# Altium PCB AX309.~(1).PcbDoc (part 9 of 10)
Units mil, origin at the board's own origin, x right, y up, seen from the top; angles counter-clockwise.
Board outline 5185 x 3614 mil, 4 copper layers (Top Layer, GND, Mid-Layer 1, Bottom Layer); 191 components, 352 nets, 1106 pads, 425 vias.
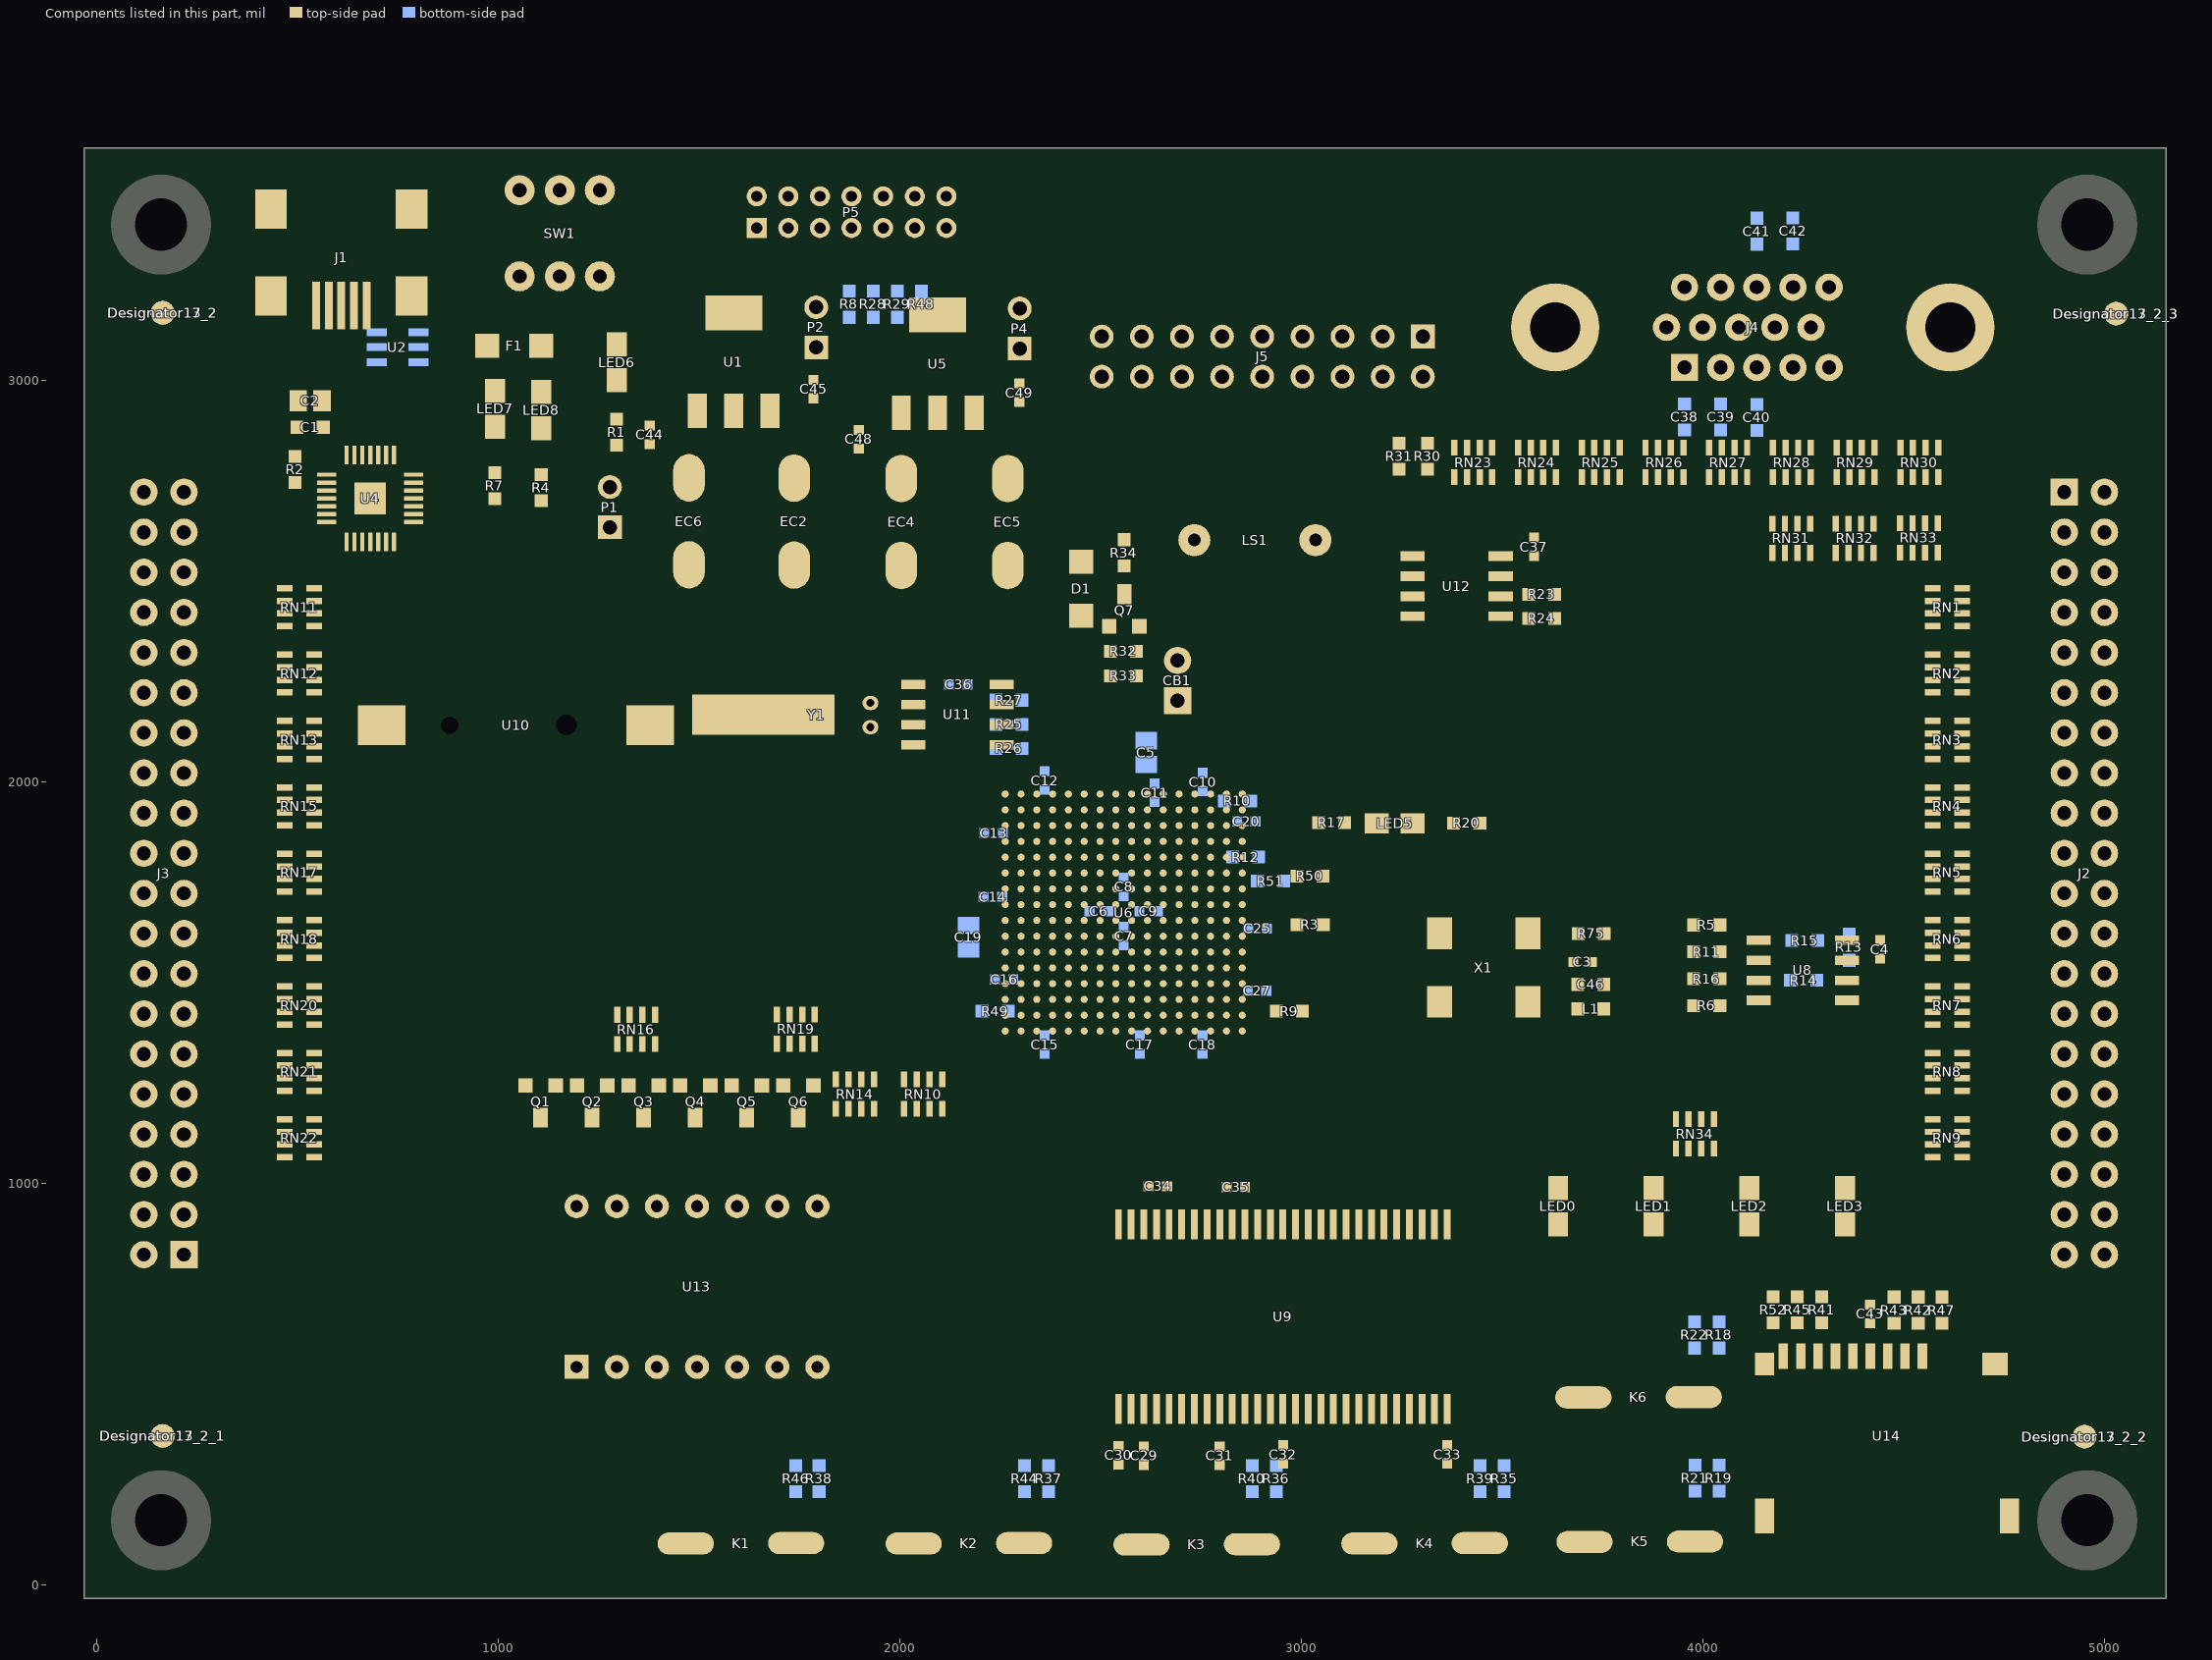
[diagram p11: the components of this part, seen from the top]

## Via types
v1: diameter 20, hole 10, Top Layer to Bottom Layer, 328 vias
v2: diameter 30, hole 15, Top Layer to Bottom Layer, 95 vias
v3: diameter 40, hole 20, Top Layer to Bottom Layer, 2 vias

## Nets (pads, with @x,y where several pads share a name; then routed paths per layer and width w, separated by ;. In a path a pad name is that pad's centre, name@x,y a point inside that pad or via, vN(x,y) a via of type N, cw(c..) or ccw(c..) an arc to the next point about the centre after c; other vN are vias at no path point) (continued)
copper on no net: (continued)
  Top Layer w0.7: 323.5,59.9 386.03,59.9 ; 323.5,60.6 386.03,60.6 ; 324.2,61.3 386.73,61.3 ; 324.2,62 387.43,62 ; 324.9,62.7 387.43,62.7 ; 324.9,63.4 388.13,63.4 ; 325.6,64.1 388.13,64.1 ; 325.6,64.8 388.83,64.8 ; 326.3,65.5 389.53,65.5 ; 326.3,66.2 389.53,66.2 ; 327,66.9 390.23,66.9 ; 327,67.6 390.93,67.6 ; 327.7,68.3 390.93,68.3 ; 327.7,69 391.63,69 ; 328.4,69.7 392.33,69.7 ; 329.1,70.4 393.03,70.4 ; 329.1,71.1 393.03,71.1 ; 329.8,71.8 393.73,71.8 ; 329.8,72.5 394.43,72.5 ; 330.5,73.2 395.13,73.2 ; 331.2,73.9 395.83,73.9 ; 331.2,74.6 395.83,74.6 ; 331.9,75.3 396.53,75.3 ; 331.9,76 397.23,76 ; 332.6,76.7 397.93,76.7 ; 333.3,77.4 398.63,77.4 ; 333.3,78.1 399.33,78.1 ; 334,78.8 400.03,78.8 ; 334.7,79.5 400.73,79.5 ; 335.4,80.2 400.73,80.2 ; 335.4,80.9 401.43,80.9 ; 336.1,81.6 402.13,81.6 ; 336.8,82.3 402.83,82.3 ; 336.8,83 403.53,83 ; 337.5,83.7 404.23,83.7 ; 338.2,84.4 404.93,84.4 ; 338.9,85.1 405.63,85.1 ; 338.9,85.8 407.03,85.8 ; 339.6,86.5 407.73,86.5 ; 340.3,87.2 408.43,87.2 ; 341,87.9 409.13,87.9 ; 341.7,88.6 409.83,88.6 ; 341.7,89.3 410.53,89.3 ; 342.4,90 411.23,90 ; 343.1,90.7 412.63,90.7 ; 343.8,91.4 413.33,91.4 ; 344.5,92.1 414.03,92.1 ; 345.2,92.8 414.73,92.8 ; 345.9,93.5 416.13,93.5 ; 345.9,94.2 416.83,94.2 ; 346.6,94.9 417.53,94.9 ; 347.3,95.6 418.93,95.6 ; 348,96.3 419.63,96.3 ; 348.7,97 421.03,97 ; 349.4,97.7 421.73,97.7 ; 350.1,98.4 423.13,98.4 ; 350.8,99.1 423.83,99.1 ; 351.5,99.8 425.23,99.8 ; 352.2,100.5 426.63,100.5 ; 352.9,101.2 427.33,101.2 ; 353.6,101.9 428.73,101.9 ; 354.3,102.6 430.13,102.6 ; 355,103.3 431.53,103.3 ; 355.7,104 432.23,104 ; 356.4,104.7 433.63,104.7 ; 357.1,105.4 435.03,105.4 ; 357.1,118.7 357.33,118.7 ; 357.8,106.1 436.43,106.1 ; 357.8,119.4 358.03,119.4 ; 357.8,120.1 359.43,120.1 ; 358.5,106.8 438.53,106.8 ; 358.5,120.8 360.13,120.8 ; 358.5,121.5 360.83,121.5 ; 359.2,122.2 361.53,122.2 ; 359.9,107.5 439.93,107.5 ; 359.9,122.9 362.23,122.9 ; 359.9,123.6 362.93,123.6 ; 360.6,108.2 441.33,108.2 ; 360.6,124.3 364.33,124.3 ; 360.6,125 365.03,125 ; 361.3,108.9 443.43,108.9 ; 361.3,125.7 365.73,125.7 ; 361.3,126.4 367.13,126.4 ; 362,109.6 444.83,109.6 ; 362,127.1 367.83,127.1 ; 362,127.8 368.53,127.8 ; 362.7,110.3 446.93,110.3 ; 362.7,128.5 369.93,128.5 ; 363.4,129.2 370.63,129.2 ; 363.4,129.9 371.33,129.9 ; 364.1,111 449.03,111 ; 364.1,130.6 372.73,130.6 ; 364.1,131.3 373.43,131.3 ; 364.8,111.7 451.13,111.7 ; 364.8,132 374.83,132 ; 364.8,132.7 375.53,132.7 ; 365.5,112.4 451.13,112.4 ; 365.5,133.4 376.93,133.4 ; 366.2,113.1 451.13,113.1 ; 366.2,134.1 377.63,134.1 ; 366.2,134.8 379.03,134.8 ; 366.9,135.5 380.43,135.5 ; 366.9,136.2 381.13,136.2 ; 367.6,113.8 451.13,113.8 ; 367.6,136.9 382.53,136.9 ; 367.6,137.6 383.93,137.6 ; 368.3,114.5 451.13,114.5 ; 368.3,138.3 384.63,138.3 ; 369,115.2 451.13,115.2 ; 369,139 386.03,139 ; 369,139.7 387.43,139.7 ; 369.7,140.4 388.83,140.4 ; 369.7,141.1 390.23,141.1 ; 370.4,115.9 451.13,115.9 ; 370.4,141.8 391.63,141.8 ; 370.4,142.5 393.03,142.5 ; 371.1,116.6 450.43,116.6 ; 371.1,143.2 394.43,143.2 ; 371.1,143.9 395.83,143.9 ; 371.8,117.3 450.43,117.3 ; 371.8,144.6 397.23,144.6 ; 372.5,145.3 399.33,145.3 ; 372.5,146 400.73,146 ; 373.2,118 450.43,118 ; 373.2,146.7 402.83,146.7 ; 373.2,147.4 404.23,147.4 ; 373.9,118.7 450.43,118.7 ; 373.9,148.1 406.33,148.1 ; 373.9,148.8 408.43,148.8 ; 374.6,149.5 409.83,149.5 ; 375.3,119.4 450.43,119.4 ; 375.3,150.2 412.63,150.2 ; 375.3,150.9 414.73,150.9 ; 376,120.1 450.43,120.1 ; 376,151.6 416.83,151.6 ; 376,152.3 419.63,152.3 ; 376.7,153 422.43,153 ; 376.7,153.7 425.23,153.7 ; 377.4,120.8 450.43,120.8 ; 377.4,154.4 428.73,154.4 ; 378.1,121.5 450.43,121.5 ; 378.1,155.1 430.83,155.1 ; 378.1,155.8 430.83,155.8 ; 378.8,156.5 431.53,156.5 ; 378.8,157.2 431.53,157.2 ; 379.5,122.2 450.43,122.2 ; 379.5,157.9 432.23,157.9 ; 379.5,158.6 432.23,158.6 ; 380.2,159.3 432.93,159.3 ; 380.2,160 432.93,160 ; 380.9,122.9 450.43,122.9 ; 380.9,160.7 432.93,160.7 ; 381.6,123.6 450.43,123.6 ; 381.6,161.4 433.63,161.4 ; 381.6,162.1 433.63,162.1 ; 382.3,162.8 434.33,162.8 ; 382.3,163.5 434.33,163.5 ; 383,124.3 450.43,124.3 ; 383,164.2 435.03,164.2 ; 383,164.9 435.03,164.9 ; 383.7,165.6 435.73,165.6 ; 384.4,125 450.43,125 ; 384.4,166.3 435.73,166.3 ; 384.4,167 436.43,167 ; 385.1,125.7 449.73,125.7 ; 385.1,167.7 436.43,167.7 ; 385.1,168.4 437.13,168.4 ; 385.8,169.1 437.13,169.1 ; 385.8,169.8 437.83,169.8 ; 386.5,126.4 449.73,126.4 ; 386.5,170.5 437.83,170.5 ; 387.2,171.2 438.53,171.2 ; 387.2,171.9 438.53,171.9 ; 387.9,127.1 449.73,127.1 ; 387.9,172.6 438.53,172.6 ; 387.9,173.3 439.23,173.3 ; 388.6,174 439.23,174 ; 388.6,174.7 439.93,174.7 ; 389.3,127.8 449.73,127.8 ; 389.3,175.4 439.93,175.4 ; 389.3,176.1 440.63,176.1 ; 390,176.8 440.63,176.8 ; 390.7,128.5 449.73,128.5 ; 390.7,177.5 441.33,177.5 ; 390.7,178.2 441.33,178.2 ; 391.4,178.9 442.03,178.9 ; 391.4,179.6 442.03,179.6 ; 392.1,129.2 449.73,129.2 ; 392.1,180.3 442.73,180.3 ; 392.1,181 442.73,181 ; 392.8,181.7 443.43,181.7 ; 393.5,129.9 449.73,129.9 ; 393.5,182.4 443.43,182.4 ; 393.5,183.1 444.13,183.1 ; 394.2,183.8 444.13,183.8 ; 394.2,184.5 444.83,184.5 ; 394.9,130.6 449.73,130.6 ; 394.9,185.2 444.83,185.2 ; 394.9,185.9 444.83,185.9 ; 395.6,186.6 445.53,186.6 ; 395.6,187.3 445.53,187.3 ; 396.3,131.3 449.73,131.3 ; 396.3,188 446.23,188 ; 397,188.7 446.23,188.7 ; 397,189.4 446.93,189.4 ; 397.7,132 449.73,132 ; 397.7,190.1 446.93,190.1 ; 397.7,190.8 447.63,190.8 ; 398.4,191.5 447.63,191.5 ; 398.4,192.2 448.33,192.2 ; 399.1,132.7 449.73,132.7 ; 399.1,192.9 448.33,192.9 ; 399.8,193.6 449.03,193.6 ; 399.8,194.3 449.03,194.3 ; 400.5,133.4 449.73,133.4 ; 400.5,195 449.73,195 ; 400.5,195.7 449.73,195.7 ; 401.2,196.4 450.43,196.4 ; 401.2,197.1 450.43,197.1 ; 401.9,197.8 497.33,197.8 ; 402.6,134.1 449.73,134.1 ; 402.6,198.5 497.33,198.5 ; 402.6,199.2 497.33,199.2 ; 403.3,199.9 497.33,199.9 ; 403.3,200.6 497.33,200.6 ; 404,134.8 449.73,134.8 ; 404,201.3 496.63,201.3 ; 404,202 496.63,202 ; 404.7,202.7 496.63,202.7 ; 404.7,203.4 496.63,203.4 ; 405.4,204.1 496.63,204.1 ; 406.1,135.5 449.03,135.5 ; 406.1,204.8 496.63,204.8 ; 406.1,205.5 495.93,205.5 ; 406.8,206.2 495.93,206.2 ; 406.8,206.9 495.93,206.9 ; 407.5,207.6 495.93,207.6 ; 407.5,208.3 495.93,208.3 ; 408.2,136.2 449.03,136.2 ; 408.2,209 495.93,209 ; 408.9,209.7 495.23,209.7 ; 408.9,210.4 495.23,210.4 ; 409.6,136.9 449.03,136.9 ; 409.6,211.1 495.23,211.1 ; 409.6,211.8 495.23,211.8 ; 410.3,212.5 495.23,212.5 ; 410.3,213.2 495.23,213.2 ; 411,213.9 494.53,213.9 ; 411.7,137.6 449.03,137.6 ; 411.7,214.6 494.53,214.6 ; 411.7,215.3 494.53,215.3 ; 412.4,216 494.53,216 ; 412.4,216.7 494.53,216.7 ; 413.1,217.4 494.53,217.4 ; 413.1,218.1 494.53,218.1 ; 413.8,138.3 449.03,138.3 ; 413.8,218.8 493.83,218.8 ; 413.8,219.5 493.83,219.5 ; 414.5,220.2 493.83,220.2 ; 415.2,220.9 493.83,220.9 ; 415.2,221.6 493.83,221.6 ; 415.9,139 449.03,139 ; 415.9,222.3 493.83,222.3 ; 415.9,223 493.13,223 ; 416.6,223.7 493.13,223.7 ; 416.6,224.4 493.13,224.4 ; 417.3,225.1 493.13,225.1 ; 418,225.8 493.13,225.8 ; 418,226.5 493.13,226.5 ; 418.7,139.7 449.03,139.7 ; 418.7,227.2 492.43,227.2 ; 418.7,227.9 492.43,227.9 ; 419.4,228.6 492.43,228.6 ; 419.4,229.3 492.43,229.3 ; 420.1,230 492.43,230 ; 420.1,230.7 492.43,230.7 ; 420.8,140.4 449.03,140.4 ; 420.8,231.4 492.43,231.4 ; 421.5,232.1 491.73,232.1 ; 421.5,232.8 491.73,232.8 ; 422.2,233.5 491.73,233.5 ; 422.2,234.2 491.73,234.2 ; 422.9,234.9 491.73,234.9 ; 422.9,235.6 491.73,235.6 ; 423.6,141.1 449.03,141.1 ; 423.6,236.3 491.03,236.3 ; 424.3,237 491.03,237 ; 424.3,237.7 491.03,237.7 ; 425,238.4 491.03,238.4 ; 425,239.1 491.03,239.1 ; 425.7,239.8 491.03,239.8 ; 425.7,240.5 490.33,240.5 ; 426.4,141.8 449.03,141.8 ; 426.4,241.2 490.33,241.2 ; 427.1,241.9 490.33,241.9 ; 427.1,242.6 490.33,242.6 ; 427.8,243.3 490.33,243.3 ; 427.8,244 490.33,244 ; 428.5,244.7 489.63,244.7 ; 428.5,245.4 489.63,245.4 ; 429.9,142.5 449.03,142.5 ; 433.4,143.2 449.03,143.2 ; 437.6,143.9 449.03,143.9 ; 442.5,144.6 448.33,144.6 ; 451.6,193.6 498.03,193.6 ; 451.6,194.3 498.03,194.3 ; 451.6,195 498.03,195 ; 451.6,195.7 498.03,195.7 ; 451.6,196.4 497.33,196.4 ; 451.6,197.1 497.33,197.1 ; 452.3,185.2 499.43,185.2 ; 452.3,185.9 499.43,185.9 ; 452.3,186.6 499.43,186.6 ; 452.3,187.3 499.43,187.3 ; 452.3,188 498.73,188 ; 452.3,188.7 498.73,188.7 ; 452.3,189.4 498.73,189.4 ; 452.3,190.1 498.73,190.1 ; 452.3,190.8 498.73,190.8 ; 452.3,191.5 498.73,191.5 ; 452.3,192.2 498.03,192.2 ; 452.3,192.9 498.03,192.9 ; 453,176.8 500.83,176.8 ; 453,177.5 500.83,177.5 ; 453,178.2 500.83,178.2 ; 453,178.9 500.13,178.9 ; 453,179.6 500.13,179.6 ; 453,180.3 500.13,180.3 ; 453,181 500.13,181 ; 453,181.7 500.13,181.7 ; 453,182.4 500.13,182.4 ; 453,183.1 499.43,183.1 ; 453,183.8 499.43,183.8 ; 453,184.5 499.43,184.5 ; 453.7,169.1 502.23,169.1 ; 453.7,169.8 502.23,169.8 ; 453.7,170.5 501.53,170.5 ; 453.7,171.2 501.53,171.2 ; 453.7,171.9 501.53,171.9 ; 453.7,172.6 501.53,172.6 ; 453.7,173.3 501.53,173.3 ; 453.7,174 501.53,174 ; 453.7,174.7 500.83,174.7 ; 453.7,175.4 500.83,175.4 ; 453.7,176.1 500.83,176.1 ; 454.4,160.7 503.63,160.7 ; 454.4,161.4 502.93,161.4 ; 454.4,162.1 502.93,162.1 ; 454.4,162.8 502.93,162.8 ; 454.4,163.5 502.93,163.5 ; 454.4,164.2 502.93,164.2 ; 454.4,164.9 502.93,164.9 ; 454.4,165.6 502.23,165.6 ; 454.4,166.3 502.23,166.3 ; 454.4,167 502.23,167 ; 454.4,167.7 502.23,167.7 ; 454.4,168.4 502.23,168.4 ; 455.1,152.3 504.33,152.3 ; 455.1,153 504.33,153 ; 455.1,153.7 504.33,153.7 ; 455.1,154.4 504.33,154.4 ; 455.1,155.1 504.33,155.1 ; 455.1,155.8 504.33,155.8 ; 455.1,156.5 504.33,156.5 ; 455.1,157.2 503.63,157.2 ; 455.1,157.9 503.63,157.9 ; 455.1,158.6 503.63,158.6 ; 455.1,159.3 503.63,159.3 ; 455.1,160 503.63,160 ; 455.8,144.6 505.73,144.6 ; 455.8,145.3 505.73,145.3 ; 455.8,146 505.73,146 ; 455.8,146.7 505.73,146.7 ; 455.8,147.4 505.73,147.4 ; 455.8,148.1 505.03,148.1 ; 455.8,148.8 505.03,148.8 ; 455.8,149.5 505.03,149.5 ; 455.8,150.2 505.03,150.2 ; 455.8,150.9 505.03,150.9 ; 455.8,151.6 505.03,151.6 ; 456.5,136.2 507.13,136.2 ; 456.5,136.9 507.13,136.9 ; 456.5,137.6 507.13,137.6 ; 456.5,138.3 507.13,138.3 ; 456.5,139 506.43,139 ; 456.5,139.7 506.43,139.7 ; 456.5,140.4 506.43,140.4 ; 456.5,141.1 506.43,141.1 ; 456.5,141.8 506.43,141.8 ; 456.5,142.5 506.43,142.5 ; 456.5,143.2 506.43,143.2 ; 456.5,143.9 505.73,143.9 ; 457.2,128.5 508.53,128.5 ; 457.2,129.2 508.53,129.2 ; 457.2,129.9 508.53,129.9 ; 457.2,130.6 507.83,130.6 ; 457.2,131.3 507.83,131.3 ; 457.2,132 507.83,132 ; 457.2,132.7 507.83,132.7 ; 457.2,133.4 507.83,133.4 ; 457.2,134.1 507.83,134.1 ; 457.2,134.8 507.13,134.8 ; 457.2,135.5 507.13,135.5 ; 457.9,120.1 509.93,120.1 ; 457.9,120.8 509.93,120.8 ; 457.9,121.5 509.23,121.5 ; 457.9,122.2 509.23,122.2 ; 457.9,122.9 509.23,122.9 ; 457.9,123.6 509.23,123.6 ; 457.9,124.3 509.23,124.3 ; 457.9,125 509.23,125 ; 457.9,125.7 509.23,125.7 ; 457.9,126.4 508.53,126.4 ; 457.9,127.1 508.53,127.1 ; 457.9,127.8 508.53,127.8 ; 458.6,112.4 511.33,112.4 ; 458.6,113.1 510.63,113.1 ; 458.6,113.8 510.63,113.8 ; 458.6,114.5 510.63,114.5 ; 458.6,115.2 510.63,115.2 ; 458.6,115.9 510.63,115.9 ; 458.6,116.6 510.63,116.6 ; 458.6,117.3 509.93,117.3 ; 458.6,118 509.93,118 ; 458.6,118.7 509.93,118.7 ; 458.6,119.4 509.93,119.4 ; 459.3,104 512.03,104 ; 459.3,104.7 512.03,104.7 ; 459.3,105.4 512.03,105.4 ; 459.3,106.1 512.03,106.1 ; 459.3,106.8 512.03,106.8 ; 459.3,107.5 512.03,107.5 ; 459.3,108.2 512.03,108.2 ; 459.3,108.9 511.33,108.9 ; 459.3,109.6 511.33,109.6 ; 459.3,110.3 511.33,110.3 ; 459.3,111 511.33,111 ; 459.3,111.7 511.33,111.7 ; 460,96.3 513.43,96.3 ; 460,97 513.43,97 ; 460,97.7 513.43,97.7 ; 460,98.4 513.43,98.4 ; 460,99.1 513.43,99.1 ; 460,99.8 512.73,99.8 ; 460,100.5 512.73,100.5 ; 460,101.2 512.73,101.2 ; 460,101.9 512.73,101.9 ; 460,102.6 512.73,102.6 ; 460,103.3 512.73,103.3 ; 460.7,87.9 514.83,87.9 ; 460.7,88.6 514.83,88.6 ; 460.7,89.3 514.83,89.3 ; 460.7,90 514.83,90 ; 460.7,90.7 514.13,90.7 ; 460.7,91.4 514.13,91.4 ; 460.7,92.1 514.13,92.1 ; 460.7,92.8 514.13,92.8 ; 460.7,93.5 514.13,93.5 ; 460.7,94.2 514.13,94.2 ; 460.7,94.9 514.13,94.9 ; 460.7,95.6 513.43,95.6 ; 461.4,80.2 516.23,80.2 ; 461.4,80.9 516.23,80.9 ; 461.4,81.6 516.23,81.6 ; 461.4,82.3 515.53,82.3 ; 461.4,83 515.53,83 ; 461.4,83.7 515.53,83.7 ; 461.4,84.4 515.53,84.4 ; 461.4,85.1 515.53,85.1 ; 461.4,85.8 515.53,85.8 ; 461.4,86.5 514.83,86.5 ; 461.4,87.2 514.83,87.2 ; 462.1,71.8 517.63,71.8 ; 462.1,72.5 517.63,72.5 ; 462.1,73.2 516.93,73.2 ; 462.1,73.9 516.93,73.9 ; 462.1,74.6 516.93,74.6 ; 462.1,75.3 516.93,75.3 ; 462.1,76 516.93,76 ; 462.1,76.7 516.93,76.7 ; 462.1,77.4 516.93,77.4 ; 462.1,78.1 516.23,78.1 ; 462.1,78.8 516.23,78.8 ; 462.1,79.5 516.23,79.5 ; 462.8,64.1 518.33,64.1 ; 462.8,64.8 518.33,64.8 ; 462.8,65.5 518.33,65.5 ; 462.8,66.2 518.33,66.2 ; 462.8,66.9 518.33,66.9 ; 462.8,67.6 518.33,67.6 ; 462.8,68.3 518.33,68.3 ; 462.8,69 517.63,69 ; 462.8,69.7 517.63,69.7 ; 462.8,70.4 517.63,70.4 ; 462.8,71.1 517.63,71.1 ; 463.5,59.9 519.03,59.9 ; 463.5,60.6 519.03,60.6 ; 463.5,61.3 519.03,61.3 ; 463.5,62 519.03,62 ; 463.5,62.7 519.03,62.7 ; 463.5,63.4 519.03,63.4 ; 558.7,59.9 708.73,59.9 ; 558.7,60.6 708.73,60.6 ; 558.7,61.3 708.73,61.3 ; 559.4,62 708.73,62 ; 559.4,62.7 708.73,62.7 ; 559.4,63.4 709.43,63.4 ; 559.4,64.1 709.43,64.1 ; 559.4,64.8 709.43,64.8 ; 560.1,65.5 709.43,65.5 ; 560.1,66.2 709.43,66.2 ; 560.1,66.9 710.13,66.9 ; 560.1,67.6 710.13,67.6 ; 560.1,68.3 710.13,68.3 ; 560.8,69 710.13,69 ; 560.8,69.7 710.13,69.7 ; 560.8,70.4 710.83,70.4 ; 560.8,71.1 710.83,71.1 ; 561.5,71.8 710.83,71.8 ; 561.5,72.5 710.83,72.5 ; 561.5,73.2 711.53,73.2 ; 561.5,73.9 711.53,73.9 ; 561.5,74.6 711.53,74.6 ; 562.2,75.3 711.53,75.3 ; 562.2,76 711.53,76 ; 562.2,76.7 712.23,76.7 ; 562.2,77.4 712.23,77.4 ; 562.2,78.1 712.23,78.1 ; 562.9,78.8 712.23,78.8 ; 562.9,79.5 712.23,79.5 ; 562.9,80.2 712.93,80.2 ; 562.9,80.9 712.93,80.9 ; 562.9,81.6 712.93,81.6 ; 563.6,82.3 712.93,82.3 ; 563.6,83 712.93,83 ; 563.6,83.7 713.63,83.7 ; 563.6,84.4 713.63,84.4 ; 564.3,85.1 713.63,85.1 ; 564.3,85.8 713.63,85.8 ; 564.3,86.5 714.33,86.5 ; 564.3,87.2 714.33,87.2 ; 564.3,87.9 714.33,87.9 ; 565,88.6 714.33,88.6 ; 565,89.3 714.33,89.3 ; 565,90 715.03,90 ; 565,90.7 715.03,90.7 ; 565,91.4 715.03,91.4 ; 565.7,92.1 715.03,92.1 ; 565.7,92.8 715.03,92.8 ; 565.7,93.5 715.73,93.5 ; 565.7,94.2 715.73,94.2 ; 566.4,94.9 715.73,94.9 ; 566.4,95.6 715.73,95.6 ; 566.4,96.3 715.73,96.3 ; 566.4,97 716.43,97 ; 566.4,97.7 716.43,97.7 ; 567.1,98.4 716.43,98.4 ; 567.1,99.1 716.43,99.1 ; 567.1,99.8 717.13,99.8 ; 567.1,100.5 717.13,100.5 ; 567.1,101.2 717.13,101.2 ; 567.8,101.9 717.13,101.9 ; 567.8,102.6 717.13,102.6 ; 567.8,103.3 717.83,103.3 ; 567.8,104 717.83,104 ; 567.8,104.7 717.83,104.7 ; 568.5,105.4 625.43,105.4 ; 568.5,106.1 625.43,106.1 ; 568.5,106.8 626.13,106.8 ; 568.5,107.5 626.13,107.5 ; 569.2,108.2 626.13,108.2 ; 569.2,108.9 626.13,108.9 ; 569.2,109.6 626.13,109.6 ; 569.2,110.3 626.83,110.3 ; 569.2,111 626.83,111 ; 569.9,111.7 626.83,111.7 ; 569.9,112.4 626.83,112.4 ; 569.9,113.1 626.83,113.1 ; 569.9,113.8 627.53,113.8 ; 569.9,114.5 627.53,114.5 ; 570.6,115.2 627.53,115.2 ; 570.6,115.9 627.53,115.9 ; 570.6,116.6 628.23,116.6 ; 570.6,117.3 628.23,117.3 ; 570.6,118 628.23,118 ; 571.3,118.7 628.23,118.7 ; 571.3,119.4 628.23,119.4 ; 571.3,120.1 628.93,120.1 ; 571.3,120.8 628.93,120.8 ; 572,121.5 628.93,121.5 ; 572,122.2 628.93,122.2 ; 572,122.9 628.93,122.9 ; 572,123.6 629.63,123.6 ; 572,124.3 629.63,124.3 ; 572.7,125 629.63,125 ; 572.7,125.7 629.63,125.7 ; 572.7,126.4 630.33,126.4 ; 572.7,127.1 630.33,127.1 ; 572.7,127.8 630.33,127.8 ; 573.4,128.5 630.33,128.5 ; 573.4,129.2 630.33,129.2 ; 573.4,129.9 631.03,129.9 ; 573.4,130.6 631.03,130.6 ; 574.1,131.3 631.03,131.3 ; 574.1,132 631.03,132 ; 574.1,132.7 631.03,132.7 ; 574.1,133.4 631.73,133.4 ; 574.1,134.1 631.73,134.1 ; 574.8,134.8 631.73,134.8 ; 574.8,135.5 631.73,135.5 ; 574.8,136.2 632.43,136.2 ; 574.8,136.9 632.43,136.9 ; 574.8,137.6 632.43,137.6 ; 575.5,138.3 632.43,138.3 ; 575.5,139 632.43,139 ; 575.5,139.7 633.13,139.7 ; 575.5,140.4 633.13,140.4 ; 576.2,141.1 633.13,141.1 ; 576.2,141.8 633.13,141.8 ; 576.2,142.5 633.13,142.5 ; 576.2,143.2 633.83,143.2 ; 576.2,143.9 633.83,143.9 ; 576.9,144.6 633.83,144.6 ; 576.9,145.3 633.83,145.3 ; 576.9,146 634.53,146 ; 576.9,146.7 634.53,146.7 ; 576.9,147.4 634.53,147.4 ; 577.6,148.1 634.53,148.1 ; 577.6,148.8 634.53,148.8 ; 577.6,149.5 635.23,149.5 ; 577.6,150.2 635.23,150.2 ; 577.6,150.9 635.23,150.9 ; 578.3,151.6 635.23,151.6 ; 578.3,152.3 635.23,152.3 ; 578.3,153 635.93,153 ; 578.3,153.7 635.93,153.7 ; 579,154.4 635.93,154.4 ; 579,155.1 635.93,155.1 ; 579,155.8 636.63,155.8 ; 579,156.5 636.63,156.5 ; 579,157.2 636.63,157.2 ; 579.7,157.9 636.63,157.9 ; 579.7,158.6 636.63,158.6 ; 579.7,159.3 637.33,159.3 ; 579.7,160 637.33,160 ; 579.7,160.7 637.33,160.7 ; 580.4,161.4 637.33,161.4 ; 580.4,162.1 637.33,162.1 ; 580.4,162.8 638.03,162.8 ; 580.4,163.5 638.03,163.5 ; 580.4,164.2 638.03,164.2 ; 581.1,164.9 638.03,164.9 ; 581.1,165.6 638.73,165.6 ; 581.1,166.3 638.73,166.3 ; 581.1,167 638.73,167 ; 581.8,167.7 638.73,167.7 ; 581.8,168.4 638.73,168.4 ; 581.8,169.1 639.43,169.1 ; 581.8,169.8 639.43,169.8 ; 581.8,170.5 639.43,170.5 ; 582.5,171.2 639.43,171.2 ; 582.5,171.9 639.43,171.9 ; 582.5,172.6 640.13,172.6 ; 582.5,173.3 640.13,173.3 ; 582.5,174 640.13,174 ; 583.2,174.7 640.13,174.7 ; 583.2,175.4 640.83,175.4 ; 583.2,176.1 640.83,176.1 ; 583.2,176.8 640.83,176.8 ; 583.9,177.5 640.83,177.5 ; 583.9,178.2 640.83,178.2 ; 583.9,178.9 641.53,178.9 ; 583.9,179.6 641.53,179.6 ; 583.9,180.3 641.53,180.3 ; 584.6,181 641.53,181 ; 584.6,181.7 641.53,181.7 ; 584.6,182.4 642.23,182.4 ; 584.6,183.1 642.23,183.1 ; 584.6,183.8 642.23,183.8 ; 585.3,184.5 642.23,184.5 ; 585.3,185.2 642.93,185.2 ; 585.3,185.9 642.93,185.9 ; 585.3,186.6 642.93,186.6 ; 586,187.3 642.93,187.3 ; 586,188 642.93,188 ; 586,188.7 643.63,188.7 ; 586,189.4 643.63,189.4 ; 586,190.1 643.63,190.1 ; 586.7,190.8 643.63,190.8 ; 586.7,191.5 643.63,191.5 ; 586.7,192.2 644.33,192.2 ; 586.7,192.9 644.33,192.9 ; 586.7,193.6 644.33,193.6 ; 587.4,194.3 644.33,194.3 ; 587.4,195 645.03,195 ; 587.4,195.7 645.03,195.7 ; 587.4,196.4 645.03,196.4 ; 587.4,197.1 645.03,197.1 ; 588.1,197.8 645.03,197.8 ; 588.1,198.5 645.73,198.5 ; 588.1,199.2 645.73,199.2 ; 588.1,199.9 645.73,199.9 ; 588.8,200.6 645.73,200.6 ; 588.8,201.3 645.73,201.3 ; 588.8,202 646.43,202 ; 588.8,202.7 646.43,202.7 ; 588.8,203.4 646.43,203.4 ; 589.5,204.1 646.43,204.1 ; 589.5,204.8 647.13,204.8 ; 589.5,205.5 647.13,205.5 ; 589.5,206.2 647.13,206.2 ; 589.5,206.9 647.13,206.9 ; 590.2,207.6 647.13,207.6 ; 590.2,208.3 647.83,208.3 ; 590.2,209 647.83,209 ; 590.2,209.7 647.83,209.7 ; 590.2,210.4 647.83,210.4 ; 590.9,211.1 647.83,211.1 ; 590.9,211.8 648.53,211.8 ; 590.9,212.5 648.53,212.5 ; 590.9,213.2 648.53,213.2 ; 591.6,213.9 648.53,213.9 ; 591.6,214.6 649.23,214.6 ; 591.6,215.3 649.23,215.3 ; 591.6,216 649.23,216 ; 591.6,216.7 649.23,216.7 ; 592.3,217.4 649.23,217.4 ; 592.3,218.1 649.93,218.1 ; 592.3,218.8 649.93,218.8 ; 592.3,219.5 649.93,219.5 ; 592.3,220.2 649.93,220.2 ; 593,220.9 649.93,220.9 ; 593,221.6 650.63,221.6 ; 593,222.3 650.63,222.3 ; 593,223 650.63,223 ; 593.7,223.7 650.63,223.7 ; 593.7,224.4 651.33,224.4 ; 593.7,225.1 651.33,225.1 ; 593.7,225.8 651.33,225.8 ; 593.7,226.5 651.33,226.5 ; 594.4,227.2 651.33,227.2 ; 594.4,227.9 652.03,227.9 ; 594.4,228.6 652.03,228.6 ; 594.4,229.3 652.03,229.3 ; 594.4,230 652.03,230 ; 595.1,230.7 652.03,230.7 ; 595.1,231.4 652.73,231.4 ; 595.1,232.1 652.73,232.1 ; 595.1,232.8 652.73,232.8 ; 595.1,233.5 652.73,233.5 ; 595.8,234.2 653.43,234.2 ; 595.8,234.9 653.43,234.9 ; 595.8,235.6 653.43,235.6 ; 595.8,236.3 653.43,236.3 ; 596.5,237 653.43,237 ; 596.5,237.7 654.13,237.7 ; 596.5,238.4 654.13,238.4 ; 596.5,239.1 654.13,239.1 ; 596.5,239.8 654.13,239.8 ; 597.2,240.5 654.83,240.5 ; 597.2,241.2 654.83,241.2 ; 597.2,241.9 654.83,241.9 ; 597.2,242.6 654.83,242.6 ; 597.2,243.3 654.83,243.3 ; 597.9,244 655.53,244 ; 597.9,244.7 655.53,244.7 ; 597.9,245.4 655.53,245.4 ; 752.6,59.9 810.23,59.9 ; 752.6,60.6 810.23,60.6 ; 752.6,61.3 810.23,61.3 ; 752.6,62 810.23,62 ; 752.6,62.7 810.93,62.7 ; 753.3,63.4 810.93,63.4 ; 753.3,64.1 810.93,64.1 ; 753.3,64.8 810.93,64.8 ; 753.3,65.5 811.63,65.5 ; 754,66.2 811.63,66.2 ; 754,66.9 811.63,66.9 ; 754,67.6 811.63,67.6 ; 754,68.3 811.63,68.3 ; 754,69 812.33,69 ; 754.7,69.7 812.33,69.7 ; 754.7,70.4 812.33,70.4 ; 754.7,71.1 812.33,71.1 ; 754.7,71.8 812.33,71.8 ; 754.7,72.5 813.03,72.5 ; 755.4,73.2 813.03,73.2 ; 755.4,73.9 813.03,73.9 ; 755.4,74.6 813.03,74.6 ; 755.4,75.3 813.73,75.3 ; 756.1,76 813.73,76 ; 756.1,76.7 813.73,76.7 ; 756.1,77.4 813.73,77.4 ; 756.1,78.1 813.73,78.1 ; 756.1,78.8 814.43,78.8 ; 756.8,79.5 814.43,79.5 ; 756.8,80.2 814.43,80.2 ; 756.8,80.9 814.43,80.9 ; 756.8,81.6 814.43,81.6 ; 756.8,82.3 815.13,82.3 ; 757.5,83 815.13,83 ; 757.5,83.7 815.13,83.7 ; 757.5,84.4 815.13,84.4 ; 757.5,85.1 815.83,85.1 ; 757.5,85.8 815.83,85.8 ; 758.2,86.5 815.83,86.5 ; 758.2,87.2 815.83,87.2 ; 758.2,87.9 815.83,87.9 ; 758.2,88.6 816.53,88.6 ; 758.9,89.3 816.53,89.3 ; 758.9,90 816.53,90 ; 758.9,90.7 816.53,90.7 ; 758.9,91.4 816.53,91.4 ; 758.9,92.1 817.23,92.1 ; 759.6,92.8 817.23,92.8 ; 759.6,93.5 817.23,93.5 ; 759.6,94.2 817.23,94.2 ; 759.6,94.9 817.93,94.9 ; 759.6,95.6 817.93,95.6 ; 760.3,96.3 817.93,96.3 ; 760.3,97 817.93,97 ; 760.3,97.7 817.93,97.7 ; 760.3,98.4 818.63,98.4 ; 761,99.1 818.63,99.1 ; 761,99.8 818.63,99.8 ; 761,100.5 818.63,100.5 ; 761,101.2 818.63,101.2 ; 761,101.9 819.33,101.9 ; 761.7,102.6 819.33,102.6 ; 761.7,103.3 819.33,103.3 ; 761.7,104 819.33,104 ; 761.7,104.7 819.33,104.7 ; 761.7,105.4 820.03,105.4 ; 762.4,106.1 820.03,106.1 ; 762.4,106.8 820.03,106.8 ; 762.4,107.5 820.03,107.5 ; 762.4,108.2 820.73,108.2 ; 763.1,108.9 820.73,108.9 ; 763.1,109.6 820.73,109.6 ; 763.1,110.3 820.73,110.3 ; 763.1,111 820.73,111 ; 763.1,111.7 821.43,111.7 ; 763.8,112.4 821.43,112.4 ; 763.8,113.1 821.43,113.1 ; 763.8,113.8 821.43,113.8 ; 763.8,114.5 821.43,114.5 ; 763.8,115.2 822.13,115.2 ; 764.5,115.9 822.13,115.9 ; 764.5,116.6 822.13,116.6 ; 764.5,117.3 822.13,117.3 ; 764.5,118 822.83,118 ; 765.2,118.7 822.83,118.7 ; 765.2,119.4 822.83,119.4 ; 765.2,120.1 822.83,120.1 ; 765.2,120.8 822.83,120.8 ; 765.2,121.5 823.53,121.5 ; 765.9,122.2 823.53,122.2 ; 765.9,122.9 823.53,122.9 ; 765.9,123.6 823.53,123.6 ; 765.9,124.3 823.53,124.3 ; 765.9,125 824.23,125 ; 766.6,125.7 824.23,125.7 ; 766.6,126.4 824.23,126.4 ; 766.6,127.1 824.23,127.1 ; 766.6,127.8 824.93,127.8 ; 767.3,128.5 824.93,128.5 ; 767.3,129.2 824.93,129.2 ; 767.3,129.9 824.93,129.9 ; 767.3,130.6 824.93,130.6 ; 767.3,131.3 825.63,131.3 ; 768,132 825.63,132 ; 768,132.7 825.63,132.7 ; 768,133.4 825.63,133.4 ; 768,134.1 826.33,134.1 ; 768,134.8 826.33,134.8 ; 768.7,135.5 826.33,135.5 ; 768.7,136.2 826.33,136.2 ; 768.7,136.9 826.33,136.9 ; 768.7,137.6 827.03,137.6 ; 769.4,138.3 827.03,138.3 ; 769.4,139 827.03,139 ; 769.4,139.7 827.03,139.7 ; 769.4,140.4 827.03,140.4 ; 769.4,141.1 827.73,141.1 ; 770.1,141.8 827.73,141.8 ; 770.1,142.5 827.73,142.5 ; 770.1,143.2 827.73,143.2 ; 770.1,143.9 828.43,143.9 ; 770.1,144.6 828.43,144.6 ; 770.8,145.3 828.43,145.3 ; 770.8,146 828.43,146 ; 770.8,146.7 828.43,146.7 ; 770.8,147.4 829.13,147.4 ; 771.5,148.1 829.13,148.1 ; 771.5,148.8 829.13,148.8 ; 771.5,149.5 829.13,149.5 ; 771.5,150.2 829.13,150.2 ; 771.5,150.9 829.83,150.9 ; 772.2,151.6 829.83,151.6 ; 772.2,152.3 829.83,152.3 ; 772.2,153 829.83,153 ; 772.2,153.7 829.83,153.7 ; 772.2,154.4 830.53,154.4 ; 772.9,155.1 830.53,155.1 ; 772.9,155.8 830.53,155.8 ; 772.9,156.5 830.53,156.5 ; 772.9,157.2 831.23,157.2 ; 773.6,157.9 831.23,157.9 ; 773.6,158.6 831.23,158.6 ; 773.6,159.3 831.23,159.3 ; 773.6,160 831.23,160 ; 773.6,160.7 831.93,160.7 ; 774.3,161.4 831.93,161.4 ; 774.3,162.1 831.93,162.1 ; 774.3,162.8 831.93,162.8 ; 774.3,163.5 831.93,163.5 ; 774.3,164.2 832.63,164.2 ; 775,164.9 832.63,164.9 ; 775,165.6 832.63,165.6 ; 775,166.3 832.63,166.3 ; 775,167 833.33,167 ; 775.7,167.7 833.33,167.7 ; 775.7,168.4 833.33,168.4 ; 775.7,169.1 833.33,169.1 ; 775.7,169.8 833.33,169.8 ; 775.7,170.5 834.03,170.5 ; 776.4,171.2 834.03,171.2 ; 776.4,171.9 834.03,171.9 ; 776.4,172.6 834.03,172.6 ; 776.4,173.3 834.73,173.3 ; 776.4,174 834.73,174 ; 777.1,174.7 834.73,174.7 ; 777.1,175.4 834.73,175.4 ; 777.1,176.1 834.73,176.1 ; 777.1,176.8 835.43,176.8 ; 777.8,177.5 835.43,177.5 ; 777.8,178.2 835.43,178.2 ; 777.8,178.9 835.43,178.9 ; 777.8,179.6 835.43,179.6 ; 777.8,180.3 836.13,180.3 ; 778.5,181 836.13,181 ; 778.5,181.7 836.13,181.7 ; 778.5,182.4 836.13,182.4 ; 778.5,183.1 836.13,183.1 ; 778.5,183.8 836.83,183.8 ; 779.2,184.5 836.83,184.5 ; 779.2,185.2 836.83,185.2 ; 779.2,185.9 836.83,185.9 ; 779.2,186.6 837.53,186.6 ; 779.9,187.3 837.53,187.3 ; 779.9,188 837.53,188 ; 779.9,188.7 837.53,188.7 ; 779.9,189.4 837.53,189.4 ; 779.9,190.1 838.23,190.1 ; 780.6,190.8 838.23,190.8 ; 780.6,191.5 838.23,191.5 ; 780.6,192.2 838.23,192.2 ; 780.6,192.9 838.23,192.9 ; 780.6,193.6 838.93,193.6 ; 781.3,194.3 838.93,194.3 ; 781.3,195 838.93,195 ; 781.3,195.7 838.93,195.7 ; 781.3,196.4 839.63,196.4 ; 782,197.1 839.63,197.1 ; 782,197.8 839.63,197.8 ; 782,198.5 839.63,198.5 ; 782,199.2 839.63,199.2 ; 782,199.9 840.33,199.9 ; 782.7,200.6 840.33,200.6 ; 782.7,201.3 840.33,201.3 ; 782.7,202 840.33,202 ; 782.7,202.7 840.33,202.7 ; 782.7,203.4 841.03,203.4 ; 783.4,204.1 841.03,204.1 ; 783.4,204.8 841.03,204.8 ; 783.4,205.5 841.03,205.5 ; 783.4,206.2 841.73,206.2 ; 784.1,206.9 841.73,206.9 ; 784.1,207.6 841.73,207.6 ; 784.1,208.3 841.73,208.3 ; 784.1,209 841.73,209 ; 784.1,209.7 842.43,209.7 ; 784.8,210.4 842.43,210.4 ; 784.8,211.1 842.43,211.1 ; 784.8,211.8 842.43,211.8 ; 784.8,212.5 843.13,212.5 ; 784.8,213.2 843.13,213.2 ; 785.5,213.9 843.13,213.9 ; 785.5,214.6 843.13,214.6 ; 785.5,215.3 843.13,215.3 ; 785.5,216 843.83,216 ; 786.2,216.7 843.83,216.7 ; 786.2,217.4 843.83,217.4 ; 786.2,218.1 843.83,218.1 ; 786.2,218.8 843.83,218.8 ; 786.2,219.5 844.53,219.5 ; 786.9,220.2 844.53,220.2 ; 786.9,220.9 844.53,220.9 ; 786.9,221.6 844.53,221.6 ; 786.9,222.3 844.53,222.3 ; 786.9,223 845.23,223 ; 787.6,223.7 845.23,223.7 ; 787.6,224.4 845.23,224.4 ; 787.6,225.1 845.23,225.1 ; 787.6,225.8 845.93,225.8 ; 788.3,226.5 845.93,226.5 ; 788.3,227.2 845.93,227.2 ; 788.3,227.9 845.93,227.9 ; 788.3,228.6 845.93,228.6 ; 788.3,229.3 846.63,229.3 ; 789,230 846.63,230 ; 789,230.7 846.63,230.7 ; 789,231.4 846.63,231.4 ; 789,232.1 846.63,232.1 ; 789,232.8 847.33,232.8 ; 789.7,233.5 847.33,233.5 ; 789.7,234.2 847.33,234.2 ; 789.7,234.9 847.33,234.9 ; 789.7,235.6 848.03,235.6 ; 790.4,236.3 848.03,236.3 ; 790.4,237 848.03,237 ; 790.4,237.7 848.03,237.7 ; 790.4,238.4 848.03,238.4 ; 790.4,239.1 848.73,239.1 ; 791.1,239.8 848.73,239.8 ; 791.1,240.5 848.73,240.5 ; 791.1,241.2 848.73,241.2 ; 791.1,241.9 848.73,241.9 ; 791.1,242.6 849.43,242.6 ; 791.8,243.3 849.43,243.3 ; 791.8,244 849.43,244 ; 791.8,244.7 849.43,244.7 ; 791.8,245.4 850.13,245.4 ; 868.1,59.9 921.53,59.9 ; 868.1,60.6 922.23,60.6 ; 868.8,61.3 922.23,61.3 ; 868.8,62 922.23,62 ; 868.8,62.7 922.23,62.7 ; 868.8,63.4 922.23,63.4 ; 868.8,64.1 922.93,64.1 ; 869.5,64.8 922.93,64.8 ; 869.5,65.5 922.93,65.5 ; 869.5,66.2 922.93,66.2 ; 869.5,66.9 923.63,66.9 ; 870.2,67.6 923.63,67.6 ; 870.2,68.3 923.63,68.3 ; 870.2,69 923.63,69 ; 870.2,69.7 923.63,69.7 ; 870.2,70.4 924.33,70.4 ; 870.9,71.1 924.33,71.1 ; 870.9,71.8 924.33,71.8 ; 870.9,72.5 924.33,72.5 ; 870.9,73.2 924.33,73.2 ; 870.9,73.9 925.03,73.9 ; 871.6,74.6 925.03,74.6 ; 871.6,75.3 925.03,75.3 ; 871.6,76 925.03,76 ; 871.6,76.7 925.73,76.7 ; 872.3,77.4 925.73,77.4 ; 872.3,78.1 925.73,78.1 ; 872.3,78.8 925.73,78.8 ; 872.3,79.5 925.73,79.5 ; 872.3,80.2 926.43,80.2 ; 873,80.9 926.43,80.9 ; 873,81.6 926.43,81.6 ; 873,82.3 926.43,82.3 ; 873,83 926.43,83 ; 873,83.7 927.13,83.7 ; 873.7,84.4 927.13,84.4 ; 873.7,85.1 927.13,85.1 ; 873.7,85.8 927.13,85.8 ; 873.7,86.5 927.83,86.5 ; 874.4,87.2 927.83,87.2 ; 874.4,87.9 927.83,87.9 ; 874.4,88.6 927.83,88.6 ; 874.4,89.3 927.83,89.3 ; 874.4,90 928.53,90 ; 875.1,90.7 928.53,90.7 ; 875.1,91.4 928.53,91.4 ; 875.1,92.1 928.53,92.1 ; 875.1,92.8 928.53,92.8 ; 875.1,93.5 929.23,93.5 ; 875.8,94.2 929.23,94.2 ; 875.8,94.9 929.23,94.9 ; 875.8,95.6 929.23,95.6 ; 875.8,96.3 929.93,96.3 ; 876.5,97 929.93,97 ; 876.5,97.7 929.93,97.7 ; 876.5,98.4 929.93,98.4 ; 876.5,99.1 929.93,99.1 ; 876.5,99.8 930.63,99.8 ; 877.2,100.5 930.63,100.5 ; 877.2,101.2 930.63,101.2 ; 877.2,101.9 930.63,101.9 ; 877.2,102.6 930.63,102.6 ; 877.2,103.3 931.33,103.3 ; 877.9,104 931.33,104 ; 877.9,104.7 931.33,104.7 ; 877.9,105.4 931.33,105.4 ; 877.9,106.1 932.03,106.1 ; 878.6,106.8 932.03,106.8 ; 878.6,107.5 932.03,107.5 ; 878.6,108.2 932.03,108.2 ; 878.6,108.9 932.03,108.9 ; 878.6,109.6 932.73,109.6 ; 879.3,110.3 932.73,110.3 ; 879.3,111 932.73,111 ; 879.3,111.7 932.73,111.7 ; 879.3,112.4 932.73,112.4 ; 880,113.1 933.43,113.1 ; 880,113.8 933.43,113.8 ; 880,114.5 933.43,114.5 ; 880,115.2 933.43,115.2 ; 880,115.9 934.13,115.9 ; 880.7,116.6 934.13,116.6 ; 880.7,117.3 934.13,117.3 ; 880.7,118 934.13,118 ; 880.7,118.7 934.13,118.7 ; 880.7,119.4 934.83,119.4 ; 881.4,120.1 934.83,120.1 ; 881.4,120.8 934.83,120.8 ; 881.4,121.5 934.83,121.5 ; 881.4,122.2 934.83,122.2 ; 882.1,122.9 935.53,122.9 ; 882.1,123.6 935.53,123.6 ; 882.1,124.3 935.53,124.3 ; 882.1,125 935.53,125 ; 882.1,125.7 935.53,125.7 ; 882.8,126.4 936.23,126.4 ; 882.8,127.1 936.23,127.1 ; 882.8,127.8 936.23,127.8 ; 882.8,128.5 936.23,128.5 ; 882.8,129.2 936.93,129.2 ; 883.5,129.9 936.93,129.9 ; 883.5,130.6 936.93,130.6 ; 883.5,131.3 936.93,131.3 ; 883.5,132 936.93,132 ; 884.2,132.7 937.63,132.7 ; 884.2,133.4 937.63,133.4 ; 884.2,134.1 937.63,134.1 ; 884.2,134.8 937.63,134.8 ; 884.2,135.5 937.63,135.5 ; 884.9,136.2 938.33,136.2 ; 884.9,136.9 938.33,136.9 ; 884.9,137.6 938.33,137.6 ; 884.9,138.3 938.33,138.3 ; 884.9,139 939.03,139 ; 885.6,139.7 939.03,139.7 ; 885.6,140.4 939.03,140.4 ; 885.6,141.1 939.03,141.1 ; 885.6,141.8 939.03,141.8 ; 886.3,142.5 939.73,142.5 ; 886.3,143.2 939.73,143.2 ; 886.3,143.9 939.73,143.9 ; 886.3,144.6 939.73,144.6 ; 886.3,145.3 939.73,145.3 ; 887,146 940.43,146 ; 887,146.7 940.43,146.7 ; 887,147.4 940.43,147.4 ; 887,148.1 940.43,148.1 ; 887,148.8 941.13,148.8 ; 887.7,149.5 941.13,149.5 ; 887.7,150.2 941.13,150.2 ; 887.7,150.9 941.13,150.9 ; 887.7,151.6 941.13,151.6 ; 888.4,152.3 941.83,152.3 ; 888.4,153 941.83,153 ; 888.4,153.7 941.83,153.7 ; 888.4,154.4 941.83,154.4 ; 888.4,155.1 941.83,155.1 ; 889.1,155.8 942.53,155.8 ; 889.1,156.5 942.53,156.5 ; 889.1,157.2 942.53,157.2 ; 889.1,157.9 942.53,157.9 ; 889.1,158.6 943.23,158.6 ; 889.8,159.3 943.23,159.3 ; 889.8,160 943.23,160 ; 889.8,160.7 943.23,160.7 ; 889.8,161.4 943.23,161.4 ; 890.5,162.1 943.93,162.1 ; 890.5,162.8 943.93,162.8 ; 890.5,163.5 943.93,163.5 ; 890.5,164.2 943.93,164.2 ; 890.5,164.9 943.93,164.9 ; 891.2,165.6 944.63,165.6 ; 891.2,166.3 944.63,166.3 ; 891.2,167 944.63,167 ; 891.2,167.7 994.33,167.7 ; 891.2,168.4 994.33,168.4 ; 891.9,169.1 993.63,169.1 ; 891.9,169.8 993.63,169.8 ; 891.9,170.5 993.63,170.5 ; 891.9,171.2 992.93,171.2 ; 892.6,171.9 992.93,171.9 ; 892.6,172.6 992.23,172.6 ; 892.6,173.3 992.23,173.3 ; 892.6,174 991.53,174 ; 892.6,174.7 991.53,174.7 ; 893.3,175.4 991.53,175.4 ; 893.3,176.1 990.83,176.1 ; 893.3,176.8 990.83,176.8 ; 893.3,177.5 990.13,177.5 ; 893.3,178.2 990.13,178.2 ; 894,178.9 989.43,178.9 ; 894,179.6 989.43,179.6 ; 894,180.3 989.43,180.3 ; 894,181 988.73,181 ; 894.7,181.7 988.73,181.7 ; 894.7,182.4 988.03,182.4 ; 894.7,183.1 988.03,183.1 ; 894.7,183.8 988.03,183.8 ; 894.7,184.5 987.33,184.5 ; 895.4,185.2 987.33,185.2 ; 895.4,185.9 986.63,185.9 ; 895.4,186.6 986.63,186.6 ; 895.4,187.3 985.93,187.3 ; 895.4,188 985.93,188 ; 896.1,188.7 985.93,188.7 ; 896.1,189.4 985.23,189.4 ; 896.1,190.1 985.23,190.1 ; 896.1,190.8 984.53,190.8 ; 896.8,191.5 984.53,191.5 ; 896.8,192.2 983.83,192.2 ; 896.8,192.9 983.83,192.9 ; 896.8,193.6 983.83,193.6 ; 896.8,194.3 983.13,194.3 ; 897.5,195 983.13,195 ; 897.5,195.7 982.43,195.7 ; 897.5,196.4 982.43,196.4 ; 897.5,197.1 981.73,197.1 ; 897.5,197.8 981.73,197.8 ; 898.2,198.5 981.73,198.5 ; 898.2,199.2 981.03,199.2 ; 898.2,199.9 981.03,199.9 ; 898.2,200.6 980.33,200.6 ; 898.9,201.3 980.33,201.3 ; 898.9,202 980.33,202 ; 898.9,202.7 979.63,202.7 ; 898.9,203.4 979.63,203.4 ; 898.9,204.1 978.93,204.1 ; 899.6,204.8 978.93,204.8 ; 899.6,205.5 978.23,205.5 ; 899.6,206.2 978.23,206.2 ; 899.6,206.9 978.23,206.9 ; 899.6,207.6 977.53,207.6 ; 900.3,208.3 977.53,208.3 ; 900.3,209 976.83,209 ; 900.3,209.7 976.83,209.7 ; 900.3,210.4 976.13,210.4 ; 901,211.1 976.13,211.1 ; 901,211.8 976.13,211.8 ; 901,212.5 975.43,212.5 ; 901,213.2 975.43,213.2 ; 901,213.9 974.73,213.9 ; 901.7,214.6 974.73,214.6 ; 901.7,215.3 974.03,215.3 ; 901.7,216 974.03,216 ; 901.7,216.7 974.03,216.7 ; 901.7,217.4 973.33,217.4 ; 902.4,218.1 973.33,218.1 ; 902.4,218.8 972.63,218.8 ; 902.4,219.5 972.63,219.5 ; 902.4,220.2 972.63,220.2 ; 903.1,220.9 971.93,220.9 ; 903.1,221.6 971.93,221.6 ; 903.1,222.3 971.23,222.3 ; 903.1,223 971.23,223 ; 903.1,223.7 970.53,223.7 ; 903.8,224.4 970.53,224.4 ; 903.8,225.1 970.53,225.1 ; 903.8,225.8 969.83,225.8 ; 903.8,226.5 969.83,226.5 ; 904.5,227.2 969.13,227.2 ; 904.5,227.9 969.13,227.9 ; 904.5,228.6 968.43,228.6 ; 904.5,229.3 968.43,229.3 ; 904.5,230 968.43,230 ; 905.2,230.7 967.73,230.7 ; 905.2,231.4 967.73,231.4 ; 905.2,232.1 967.03,232.1 ; 905.2,232.8 967.03,232.8 ; 905.2,233.5 966.33,233.5 ; 905.9,234.2 966.33,234.2 ; 905.9,234.9 966.33,234.9 ; 905.9,235.6 965.63,235.6 ; 905.9,236.3 965.63,236.3 ; 906.6,237 964.93,237 ; 906.6,237.7 964.93,237.7 ; 906.6,238.4 964.93,238.4 ; 906.6,239.1 964.23,239.1 ; 906.6,239.8 964.23,239.8 ; 907.3,240.5 963.53,240.5 ; 907.3,241.2 963.53,241.2 ; 907.3,241.9 962.83,241.9 ; 907.3,242.6 962.83,242.6 ; 907.3,243.3 962.83,243.3 ; 908,244 962.13,244 ; 908,244.7 962.13,244.7 ; 908,245.4 961.43,245.4 ; 946.5,165.6 995.73,165.6 ; 946.5,166.3 995.03,166.3 ; 946.5,167 995.03,167 ; 947.2,164.2 995.73,164.2 ; 947.2,164.9 995.73,164.9 ; 947.9,162.8 996.43,162.8 ; 947.9,163.5 996.43,163.5 ; 948.6,160.7 997.13,160.7 ; 948.6,161.4 997.13,161.4 ; 948.6,162.1 997.13,162.1 ; 949.3,159.3 997.83,159.3 ; 949.3,160 997.83,160 ; 950,157.9 998.53,157.9 ; 950,158.6 998.53,158.6 ; 950.7,155.8 999.23,155.8 ; 950.7,156.5 999.23,156.5 ; 950.7,157.2 999.23,157.2 ; 951.4,154.4 999.93,154.4 ; 951.4,155.1 999.93,155.1 ; 952.1,152.3 1001.33,152.3 ; 952.1,153 1000.63,153 ; 952.1,153.7 1000.63,153.7 ; 952.8,150.9 1001.33,150.9 ; 952.8,151.6 1001.33,151.6 ; 953.5,149.5 1002.03,149.5 ; 953.5,150.2 1002.03,150.2 ; 954.2,147.4 1002.73,147.4 ; 954.2,148.1 1002.73,148.1 ; 954.2,148.8 1002.73,148.8 ; 954.9,146 1003.43,146 ; 954.9,146.7 1003.43,146.7 ; 955.6,144.6 1004.13,144.6 ; 955.6,145.3 1004.13,145.3 ; 956.3,142.5 1004.83,142.5 ; 956.3,143.2 1004.83,143.2 ; 956.3,143.9 1004.83,143.9 ; 957,141.1 1005.53,141.1 ; 957,141.8 1005.53,141.8 ; 957.7,139.7 1006.23,139.7 ; 957.7,140.4 1006.23,140.4 ; 958.4,137.6 1006.93,137.6 ; 958.4,138.3 1006.93,138.3 ; 958.4,139 1006.93,139 ; 959.1,136.2 1062.23,136.2 ; 959.1,136.9 1062.23,136.9 ; 959.8,134.8 1061.53,134.8 ; 959.8,135.5 1061.53,135.5 ; 960.5,132.7 1061.53,132.7 ; 960.5,133.4 1061.53,133.4 ; 960.5,134.1 1061.53,134.1 ; 961.2,131.3 1060.83,131.3 ; 961.2,132 1060.83,132 ; 961.9,129.9 1060.83,129.9 ; 961.9,130.6 1060.83,130.6 ; 962.6,127.8 1060.13,127.8 ; 962.6,128.5 1060.13,128.5 ; 962.6,129.2 1060.83,129.2 ; 963.3,126.4 1060.13,126.4 ; 963.3,127.1 1060.13,127.1 ; 964,125 1059.43,125 ; 964,125.7 1059.43,125.7 ; 964.7,122.9 1059.43,122.9 ; 964.7,123.6 1059.43,123.6 ; 964.7,124.3 1059.43,124.3 ; 965.4,121.5 1058.73,121.5 ; 965.4,122.2 1058.73,122.2 ; 966.1,120.1 1058.73,120.1 ; 966.1,120.8 1058.73,120.8 ; 966.8,118 1058.03,118 ; 966.8,118.7 1058.03,118.7 ; 966.8,119.4 1058.73,119.4 ; 967.5,116.6 1058.03,116.6 ; 967.5,117.3 1058.03,117.3 ; 968.2,115.2 1057.33,115.2 ; 968.2,115.9 1057.33,115.9 ; 968.9,113.1 1057.33,113.1 ; 968.9,113.8 1057.33,113.8 ; 968.9,114.5 1057.33,114.5 ; 969.6,111.7 1056.63,111.7 ; 969.6,112.4 1056.63,112.4 ; 970.3,110.3 1056.63,110.3 ; 970.3,111 1056.63,111 ; 971,108.2 1055.93,108.2 ; 971,108.9 1055.93,108.9 ; 971,109.6 1056.63,109.6 ; 971.7,106.8 1055.93,106.8 ; 971.7,107.5 1055.93,107.5 ; 972.4,104.7 1055.23,104.7 ; 972.4,105.4 1055.23,105.4 ; 972.4,106.1 1055.23,106.1 ; 973.1,103.3 1055.23,103.3 ; 973.1,104 1055.23,104 ; 973.8,101.9 1054.53,101.9 ; 973.8,102.6 1054.53,102.6 ; 974.5,99.8 1053.83,99.8 ; 974.5,100.5 1054.53,100.5 ; 974.5,101.2 1054.53,101.2 ; 975.2,98.4 1053.83,98.4 ; 975.2,99.1 1053.83,99.1 ; 975.9,97 1053.83,97 ; 975.9,97.7 1053.83,97.7 ; 976.6,94.9 1053.13,94.9 ; 976.6,95.6 1053.13,95.6 ; 976.6,96.3 1053.13,96.3 ; 977.3,93.5 1053.13,93.5 ; 977.3,94.2 1053.13,94.2 ; 978,92.1 1052.43,92.1 ; 978,92.8 1052.43,92.8 ; 978.7,90 1052.43,90 ; 978.7,90.7 1052.43,90.7 ; 978.7,91.4 1052.43,91.4 ; 979.4,88.6 1051.73,88.6 ; 979.4,89.3 1051.73,89.3 ; 980.1,87.2 1051.73,87.2 ; 980.1,87.9 1051.73,87.9 ; 980.8,85.1 1051.03,85.1 ; 980.8,85.8 1051.03,85.8 ; 980.8,86.5 1051.03,86.5 ; 981.5,83.7 1051.03,83.7 ; 981.5,84.4 1051.03,84.4 ; 982.2,82.3 1050.33,82.3 ; 982.2,83 1050.33,83 ; 982.9,80.2 1049.63,80.2 ; 982.9,80.9 1050.33,80.9 ; 982.9,81.6 1050.33,81.6 ; 983.6,78.8 1049.63,78.8 ; 983.6,79.5 1049.63,79.5 ; 984.3,77.4 1049.63,77.4 ; 984.3,78.1 1049.63,78.1 ; 985,75.3 1048.93,75.3 ; 985,76 1048.93,76 ; 985,76.7 1048.93,76.7 ; 985.7,73.9 1048.93,73.9 ; 985.7,74.6 1048.93,74.6 ; 986.4,72.5 1048.23,72.5 ; 986.4,73.2 1048.23,73.2 ; 987.1,70.4 1047.53,70.4 ; 987.1,71.1 1048.23,71.1 ; 987.1,71.8 1048.23,71.8 ; 987.8,69 1047.53,69 ; 987.8,69.7 1047.53,69.7 ; 988.5,67.6 1047.53,67.6 ; 988.5,68.3 1047.53,68.3 ; 989.2,65.5 1046.83,65.5 ; 989.2,66.2 1046.83,66.2 ; 989.2,66.9 1046.83,66.9 ; 989.9,64.1 1046.83,64.1 ; 989.9,64.8 1046.83,64.8 ; 990.6,62 1046.13,62 ; 990.6,62.7 1046.13,62.7 ; 990.6,63.4 1046.13,63.4 ; 991.3,60.6 1045.43,60.6 ; 991.3,61.3 1046.13,61.3 ; 992,59.9 1045.43,59.9 ; 1008.8,137.6 1062.23,137.6 ; 1008.8,138.3 1062.23,138.3 ; 1008.8,139 1062.93,139 ; 1008.8,139.7 1062.93,139.7 ; 1009.5,140.4 1062.93,140.4 ; 1009.5,141.1 1062.93,141.1 ; 1009.5,141.8 1062.93,141.8 ; 1009.5,142.5 1063.63,142.5 ; 1010.2,143.2 1063.63,143.2 ; 1010.2,143.9 1063.63,143.9 ; 1010.2,144.6 1063.63,144.6 ; 1010.2,145.3 1064.33,145.3 ; 1010.2,146 1064.33,146 ; 1010.9,146.7 1064.33,146.7 ; 1010.9,147.4 1064.33,147.4 ; 1010.9,148.1 1064.33,148.1 ; 1010.9,148.8 1065.03,148.8 ; 1010.9,149.5 1065.03,149.5 ; 1011.6,150.2 1065.03,150.2 ; 1011.6,150.9 1065.03,150.9 ; 1011.6,151.6 1065.03,151.6 ; 1011.6,152.3 1065.73,152.3 ; 1011.6,153 1065.73,153 ; 1012.3,153.7 1065.73,153.7 ; 1012.3,154.4 1065.73,154.4 ; 1012.3,155.1 1065.73,155.1 ; 1012.3,155.8 1066.43,155.8 ; 1013,156.5 1066.43,156.5 ; 1013,157.2 1066.43,157.2 ; 1013,157.9 1066.43,157.9 ; 1013,158.6 1067.13,158.6 ; 1013,159.3 1067.13,159.3 ; 1013.7,160 1067.13,160 ; 1013.7,160.7 1067.13,160.7 ; 1013.7,161.4 1067.13,161.4 ; 1013.7,162.1 1067.83,162.1 ; 1014.4,162.8 1067.83,162.8 ; 1014.4,163.5 1067.83,163.5 ; 1014.4,164.2 1067.83,164.2 ; 1014.4,164.9 1067.83,164.9 ; 1014.4,165.6 1068.53,165.6 ; 1015.1,166.3 1068.53,166.3 ; 1015.1,167 1068.53,167 ; 1015.1,167.7 1068.53,167.7 ; 1015.1,168.4 1069.23,168.4 ; 1015.1,169.1 1069.23,169.1 ; 1015.8,169.8 1069.23,169.8 ; 1015.8,170.5 1069.23,170.5 ; 1015.8,171.2 1069.23,171.2 ; 1015.8,171.9 1069.93,171.9 ; 1016.5,172.6 1069.93,172.6 ; 1016.5,173.3 1069.93,173.3 ; 1016.5,174 1069.93,174 ; 1016.5,174.7 1069.93,174.7 ; 1016.5,175.4 1070.63,175.4 ; 1017.2,176.1 1070.63,176.1 ; 1017.2,176.8 1070.63,176.8 ; 1017.2,177.5 1070.63,177.5 ; 1017.2,178.2 1071.33,178.2 ; 1017.2,178.9 1071.33,178.9 ; 1017.9,179.6 1071.33,179.6 ; 1017.9,180.3 1071.33,180.3 ; 1017.9,181 1071.33,181 ; 1017.9,181.7 1072.03,181.7 ; 1018.6,182.4 1072.03,182.4 ; 1018.6,183.1 1072.03,183.1 ; 1018.6,183.8 1072.03,183.8 ; 1018.6,184.5 1072.73,184.5 ; 1018.6,185.2 1072.73,185.2 ; 1019.3,185.9 1072.73,185.9 ; 1019.3,186.6 1072.73,186.6 ; 1019.3,187.3 1072.73,187.3 ; 1019.3,188 1073.43,188 ; 1019.3,188.7 1073.43,188.7 ; 1020,189.4 1073.43,189.4 ; 1020,190.1 1073.43,190.1 ; 1020,190.8 1073.43,190.8 ; 1020,191.5 1074.13,191.5 ; 1020.7,192.2 1074.13,192.2 ; 1020.7,192.9 1074.13,192.9 ; 1020.7,193.6 1074.13,193.6 ; 1020.7,194.3 1074.83,194.3 ; 1020.7,195 1074.83,195 ; 1021.4,195.7 1074.83,195.7 ; 1021.4,196.4 1074.83,196.4 ; 1021.4,197.1 1074.83,197.1 ; 1021.4,197.8 1075.53,197.8 ; 1022.1,198.5 1075.53,198.5 ; 1022.1,199.2 1075.53,199.2 ; 1022.1,199.9 1075.53,199.9 ; 1022.1,200.6 1075.53,200.6 ; 1022.1,201.3 1076.23,201.3 ; 1022.8,202 1076.23,202 ; 1022.8,202.7 1076.23,202.7 ; 1022.8,203.4 1076.23,203.4 ; 1022.8,204.1 1076.93,204.1 ; 1022.8,204.8 1076.93,204.8 ; 1023.5,205.5 1076.93,205.5 ; 1023.5,206.2 1076.93,206.2 ; 1023.5,206.9 1076.93,206.9 ; 1023.5,207.6 1077.63,207.6 ; 1024.2,208.3 1077.63,208.3 ; 1024.2,209 1077.63,209 ; 1024.2,209.7 1077.63,209.7 ; 1024.2,210.4 1077.63,210.4 ; 1024.2,211.1 1078.33,211.1 ; 1024.9,211.8 1078.33,211.8 ; 1024.9,212.5 1078.33,212.5 ; 1024.9,213.2 1078.33,213.2 ; 1024.9,213.9 1079.03,213.9 ; 1024.9,214.6 1079.03,214.6 ; 1025.6,215.3 1079.03,215.3 ; 1025.6,216 1079.03,216 ; 1025.6,216.7 1079.03,216.7 ; 1025.6,217.4 1079.73,217.4 ; 1026.3,218.1 1079.73,218.1 ; 1026.3,218.8 1079.73,218.8 ; 1026.3,219.5 1079.73,219.5 ; 1026.3,220.2 1079.73,220.2 ; 1026.3,220.9 1080.43,220.9 ; 1027,221.6 1080.43,221.6 ; 1027,222.3 1080.43,222.3 ; 1027,223 1080.43,223 ; 1027,223.7 1081.13,223.7 ; 1027,224.4 1081.13,224.4 ; 1027.7,225.1 1081.13,225.1 ; 1027.7,225.8 1081.13,225.8 ; 1027.7,226.5 1081.13,226.5 ; 1027.7,227.2 1081.83,227.2 ; 1028.4,227.9 1081.83,227.9 ; 1028.4,228.6 1081.83,228.6 ; 1028.4,229.3 1081.83,229.3 ; 1028.4,230 1081.83,230 ; 1028.4,230.7 1082.53,230.7 ; 1029.1,231.4 1082.53,231.4 ; 1029.1,232.1 1082.53,232.1 ; 1029.1,232.8 1082.53,232.8 ; 1029.1,233.5 1083.23,233.5 ; 1029.1,234.2 1083.23,234.2 ; 1029.8,234.9 1083.23,234.9 ; 1029.8,235.6 1083.23,235.6 ; 1029.8,236.3 1083.23,236.3 ; 1029.8,237 1083.93,237 ; 1030.5,237.7 1083.93,237.7 ; 1030.5,238.4 1083.93,238.4 ; 1030.5,239.1 1083.93,239.1 ; 1030.5,239.8 1083.93,239.8 ; 1030.5,240.5 1084.63,240.5 ; 1031.2,241.2 1084.63,241.2 ; 1031.2,241.9 1084.63,241.9 ; 1031.2,242.6 1084.63,242.6 ; 1031.2,243.3 1085.33,243.3 ; 1031.2,244 1085.33,244 ; 1031.9,244.7 1085.33,244.7 ; 1031.9,245.4 1085.33,245.4 ; 1085.1,59.9 1154.63,59.9 ; 1085.8,60.6 1155.33,60.6 ; 1085.8,61.3 1156.03,61.3 ; 1086.5,62 1156.73,62 ; 1087.2,62.7 1157.43,62.7 ; 1087.9,63.4 1158.13,63.4 ; 1088.6,64.1 1158.13,64.1 ; 1089.3,64.8 1158.83,64.8 ; 1090,65.5 1159.53,65.5 ; 1090.7,66.2 1160.23,66.2 ; 1091.4,66.9 1160.93,66.9 ; 1092.1,67.6 1161.63,67.6 ; 1092.8,68.3 1162.33,68.3 ; 1093.5,69 1162.33,69 ; 1093.5,69.7 1163.03,69.7 ; 1094.2,70.4 1163.73,70.4 ; 1094.9,71.1 1164.43,71.1 ; 1095.6,71.8 1165.13,71.8 ; 1096.3,72.5 1165.83,72.5 ; 1097,73.2 1166.53,73.2 ; 1097.7,73.9 1166.53,73.9 ; 1098.4,74.6 1167.23,74.6 ; 1099.1,75.3 1167.93,75.3 ; 1099.8,76 1168.63,76 ; 1100.5,76.7 1169.33,76.7 ; 1100.5,77.4 1170.03,77.4 ; 1101.2,78.1 1170.73,78.1 ; 1101.9,78.8 1170.73,78.8 ; 1102.6,79.5 1171.43,79.5 ; 1103.3,80.2 1172.13,80.2 ; 1104,80.9 1172.83,80.9 ; 1104.7,81.6 1173.53,81.6 ; 1105.4,82.3 1174.23,82.3 ; 1106.1,83 1174.93,83 ; 1106.8,83.7 1174.93,83.7 ; 1107.5,84.4 1175.63,84.4 ; 1108.2,85.1 1176.33,85.1 ; 1108.2,85.8 1177.03,85.8 ; 1108.9,86.5 1177.73,86.5 ; 1109.6,87.2 1178.43,87.2 ; 1110.3,87.9 1179.13,87.9 ; 1111,88.6 1179.13,88.6 ; 1111.7,89.3 1179.83,89.3 ; 1112.4,90 1180.53,90 ; 1113.1,90.7 1181.23,90.7 ; 1113.8,91.4 1181.93,91.4 ; 1114.5,92.1 1182.63,92.1 ; 1115.2,92.8 1182.63,92.8 ; 1115.2,93.5 1183.33,93.5 ; 1115.9,94.2 1184.03,94.2 ; 1116.6,94.9 1184.73,94.9 ; 1117.3,95.6 1185.43,95.6 ; 1118,96.3 1186.13,96.3 ; 1118.7,97 1186.83,97 ; 1119.4,97.7 1187.53,97.7 ; 1120.1,98.4 1187.53,98.4 ; 1120.8,99.1 1188.23,99.1 ; 1121.5,99.8 1188.93,99.8 ; 1122.2,100.5 1189.63,100.5 ; 1122.2,101.2 1190.33,101.2 ; 1122.9,101.9 1191.03,101.9 ; 1123.6,102.6 1191.73,102.6 ; 1124.3,103.3 1191.73,103.3 ; 1125,104 1192.43,104 ; 1125.7,104.7 1193.13,104.7 ; 1125.7,244.7 1184.73,244.7 ; 1125.7,245.4 1184.73,245.4 ; 1126.4,105.4 1193.83,105.4 ; 1126.4,243.3 1185.43,243.3 ; 1126.4,244 1185.43,244 ; 1127.1,106.1 1194.53,106.1 ; 1127.1,242.6 1186.13,242.6 ; 1127.8,106.8 1195.23,106.8 ; 1127.8,241.2 1186.83,241.2 ; 1127.8,241.9 1186.13,241.9 ; 1128.5,107.5 1195.23,107.5 ; 1128.5,239.8 1187.53,239.8 ; 1128.5,240.5 1186.83,240.5 ; 1129.2,108.2 1195.93,108.2 ; 1129.2,238.4 1188.23,238.4 ; 1129.2,239.1 1187.53,239.1 ; 1129.9,108.9 1196.63,108.9 ; 1129.9,109.6 1197.33,109.6 ; 1129.9,237.7 1188.93,237.7 ; 1130.6,110.3 1198.03,110.3 ; 1130.6,236.3 1189.63,236.3 ; 1130.6,237 1188.93,237 ; 1131.3,111 1198.73,111 ; 1131.3,234.9 1190.33,234.9 ; 1131.3,235.6 1189.63,235.6 ; 1132,111.7 1198.73,111.7 ; 1132,233.5 1191.03,233.5 ; 1132,234.2 1190.33,234.2 ; 1132.7,112.4 1198.73,112.4 ; 1132.7,232.8 1191.03,232.8 ; 1133.4,113.1 1198.03,113.1 ; 1133.4,231.4 1191.73,231.4 ; 1133.4,232.1 1191.73,232.1 ; 1134.1,113.8 1198.03,113.8 ; 1134.1,230 1192.43,230 ; 1134.1,230.7 1192.43,230.7 ; 1134.8,114.5 1197.33,114.5 ; 1134.8,228.6 1193.13,228.6 ; 1134.8,229.3 1193.13,229.3 ; 1135.5,115.2 1197.33,115.2 ; 1135.5,227.9 1193.83,227.9 ; 1136.2,115.9 1196.63,115.9 ; 1136.2,226.5 1194.53,226.5 ; 1136.2,227.2 1193.83,227.2 ; 1136.9,116.6 1196.63,116.6 ; 1136.9,117.3 1195.93,117.3 ; 1136.9,225.1 1195.23,225.1 ; 1136.9,225.8 1194.53,225.8 ; 1137.6,118 1195.93,118 ; 1137.6,223.7 1195.93,223.7 ; 1137.6,224.4 1195.23,224.4 ; 1138.3,118.7 1195.23,118.7 ; 1138.3,222.3 1196.63,222.3 ; 1138.3,223 1195.93,223 ; 1139,119.4 1195.23,119.4 ; 1139,221.6 1196.63,221.6 ; 1139.7,120.1 1194.53,120.1 ; 1139.7,220.2 1197.33,220.2 ; 1139.7,220.9 1197.33,220.9 ; 1140.4,120.8 1194.53,120.8 ; 1140.4,218.8 1198.03,218.8 ; 1140.4,219.5 1198.03,219.5 ; 1141.1,121.5 1193.83,121.5 ; 1141.1,217.4 1198.73,217.4 ; 1141.1,218.1 1198.73,218.1 ; 1141.8,122.2 1193.83,122.2 ; 1141.8,216.7 1199.43,216.7 ; 1142.5,122.9 1193.13,122.9 ; 1142.5,215.3 1200.13,215.3 ; 1142.5,216 1199.43,216 ; 1143.2,123.6 1193.13,123.6 ; 1143.2,213.9 1200.83,213.9 ; 1143.2,214.6 1200.83,214.6 ; 1143.9,124.3 1192.43,124.3 ; 1143.9,212.5 1201.53,212.5 ; 1143.9,213.2 1201.53,213.2 ; 1144.6,125 1191.73,125 ; 1144.6,125.7 1191.73,125.7 ; 1144.6,211.8 1202.23,211.8 ; 1145.3,126.4 1191.03,126.4 ; 1145.3,210.4 1202.93,210.4 ; 1145.3,211.1 1202.23,211.1 ; 1146,127.1 1191.03,127.1 ; 1146,209 1203.63,209 ; 1146,209.7 1202.93,209.7 ; 1146.7,127.8 1190.33,127.8 ; 1146.7,207.6 1204.33,207.6 ; 1146.7,208.3 1203.63,208.3 ; 1147.4,128.5 1190.33,128.5 ; 1147.4,206.9 1204.33,206.9 ; 1148.1,129.2 1189.63,129.2 ; 1148.1,205.5 1205.03,205.5 ; 1148.1,206.2 1205.03,206.2 ; 1148.8,129.9 1189.63,129.9 ; 1148.8,204.1 1205.73,204.1 ; 1148.8,204.8 1205.73,204.8 ; 1149.5,130.6 1188.93,130.6 ; 1149.5,202.7 1206.43,202.7 ; 1149.5,203.4 1206.43,203.4 ; 1150.2,131.3 1188.93,131.3 ; 1150.2,201.3 1207.13,201.3 ; 1150.2,202 1207.13,202 ; 1150.9,132 1188.23,132 ; 1150.9,200.6 1207.83,200.6 ; 1151.6,132.7 1188.23,132.7 ; 1151.6,133.4 1187.53,133.4 ; 1151.6,199.2 1208.53,199.2 ; 1151.6,199.9 1207.83,199.9 ; 1152.3,134.1 1187.53,134.1 ; 1152.3,197.8 1209.23,197.8 ; 1152.3,198.5 1208.53,198.5 ; 1153,134.8 1186.83,134.8 ; 1153,196.4 1209.93,196.4 ; 1153,197.1 1209.23,197.1 ; 1153.7,135.5 1186.83,135.5 ; 1153.7,195.7 1209.93,195.7 ; 1154.4,136.2 1186.13,136.2 ; 1154.4,194.3 1210.63,194.3 ; 1154.4,195 1210.63,195 ; 1155.1,136.9 1186.13,136.9 ; 1155.1,192.9 1209.93,192.9 ; 1155.1,193.6 1210.63,193.6 ; 1155.8,137.6 1185.43,137.6 ; 1155.8,191.5 1208.53,191.5 ; 1155.8,192.2 1209.23,192.2 ; 1156.5,138.3 1185.43,138.3 ; 1156.5,190.8 1207.83,190.8 ; 1157.2,139 1184.73,139 ; 1157.2,189.4 1206.43,189.4 ; 1157.2,190.1 1207.13,190.1 ; 1157.9,139.7 1184.03,139.7 ; 1157.9,188 1205.03,188 ; 1157.9,188.7 1205.73,188.7 ; 1158.6,140.4 1184.03,140.4 ; 1158.6,186.6 1203.63,186.6 ; 1158.6,187.3 1204.33,187.3 ; 1159.3,141.1 1183.33,141.1 ; 1159.3,141.8 1183.33,141.8 ; 1159.3,185.9 1202.93,185.9 ; 1160,142.5 1182.63,142.5 ; 1160,184.5 1201.53,184.5 ; 1160,185.2 1202.23,185.2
